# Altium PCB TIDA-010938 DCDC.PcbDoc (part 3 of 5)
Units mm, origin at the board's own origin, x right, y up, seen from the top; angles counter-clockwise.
Board outline 275 x 165 mm, 4 copper layers (Top Layer, Layer 1, Layer 2, Bottom Layer), stack 1.787 mm thick; 436 components, 216 nets, 1367 pads, 1992 vias.
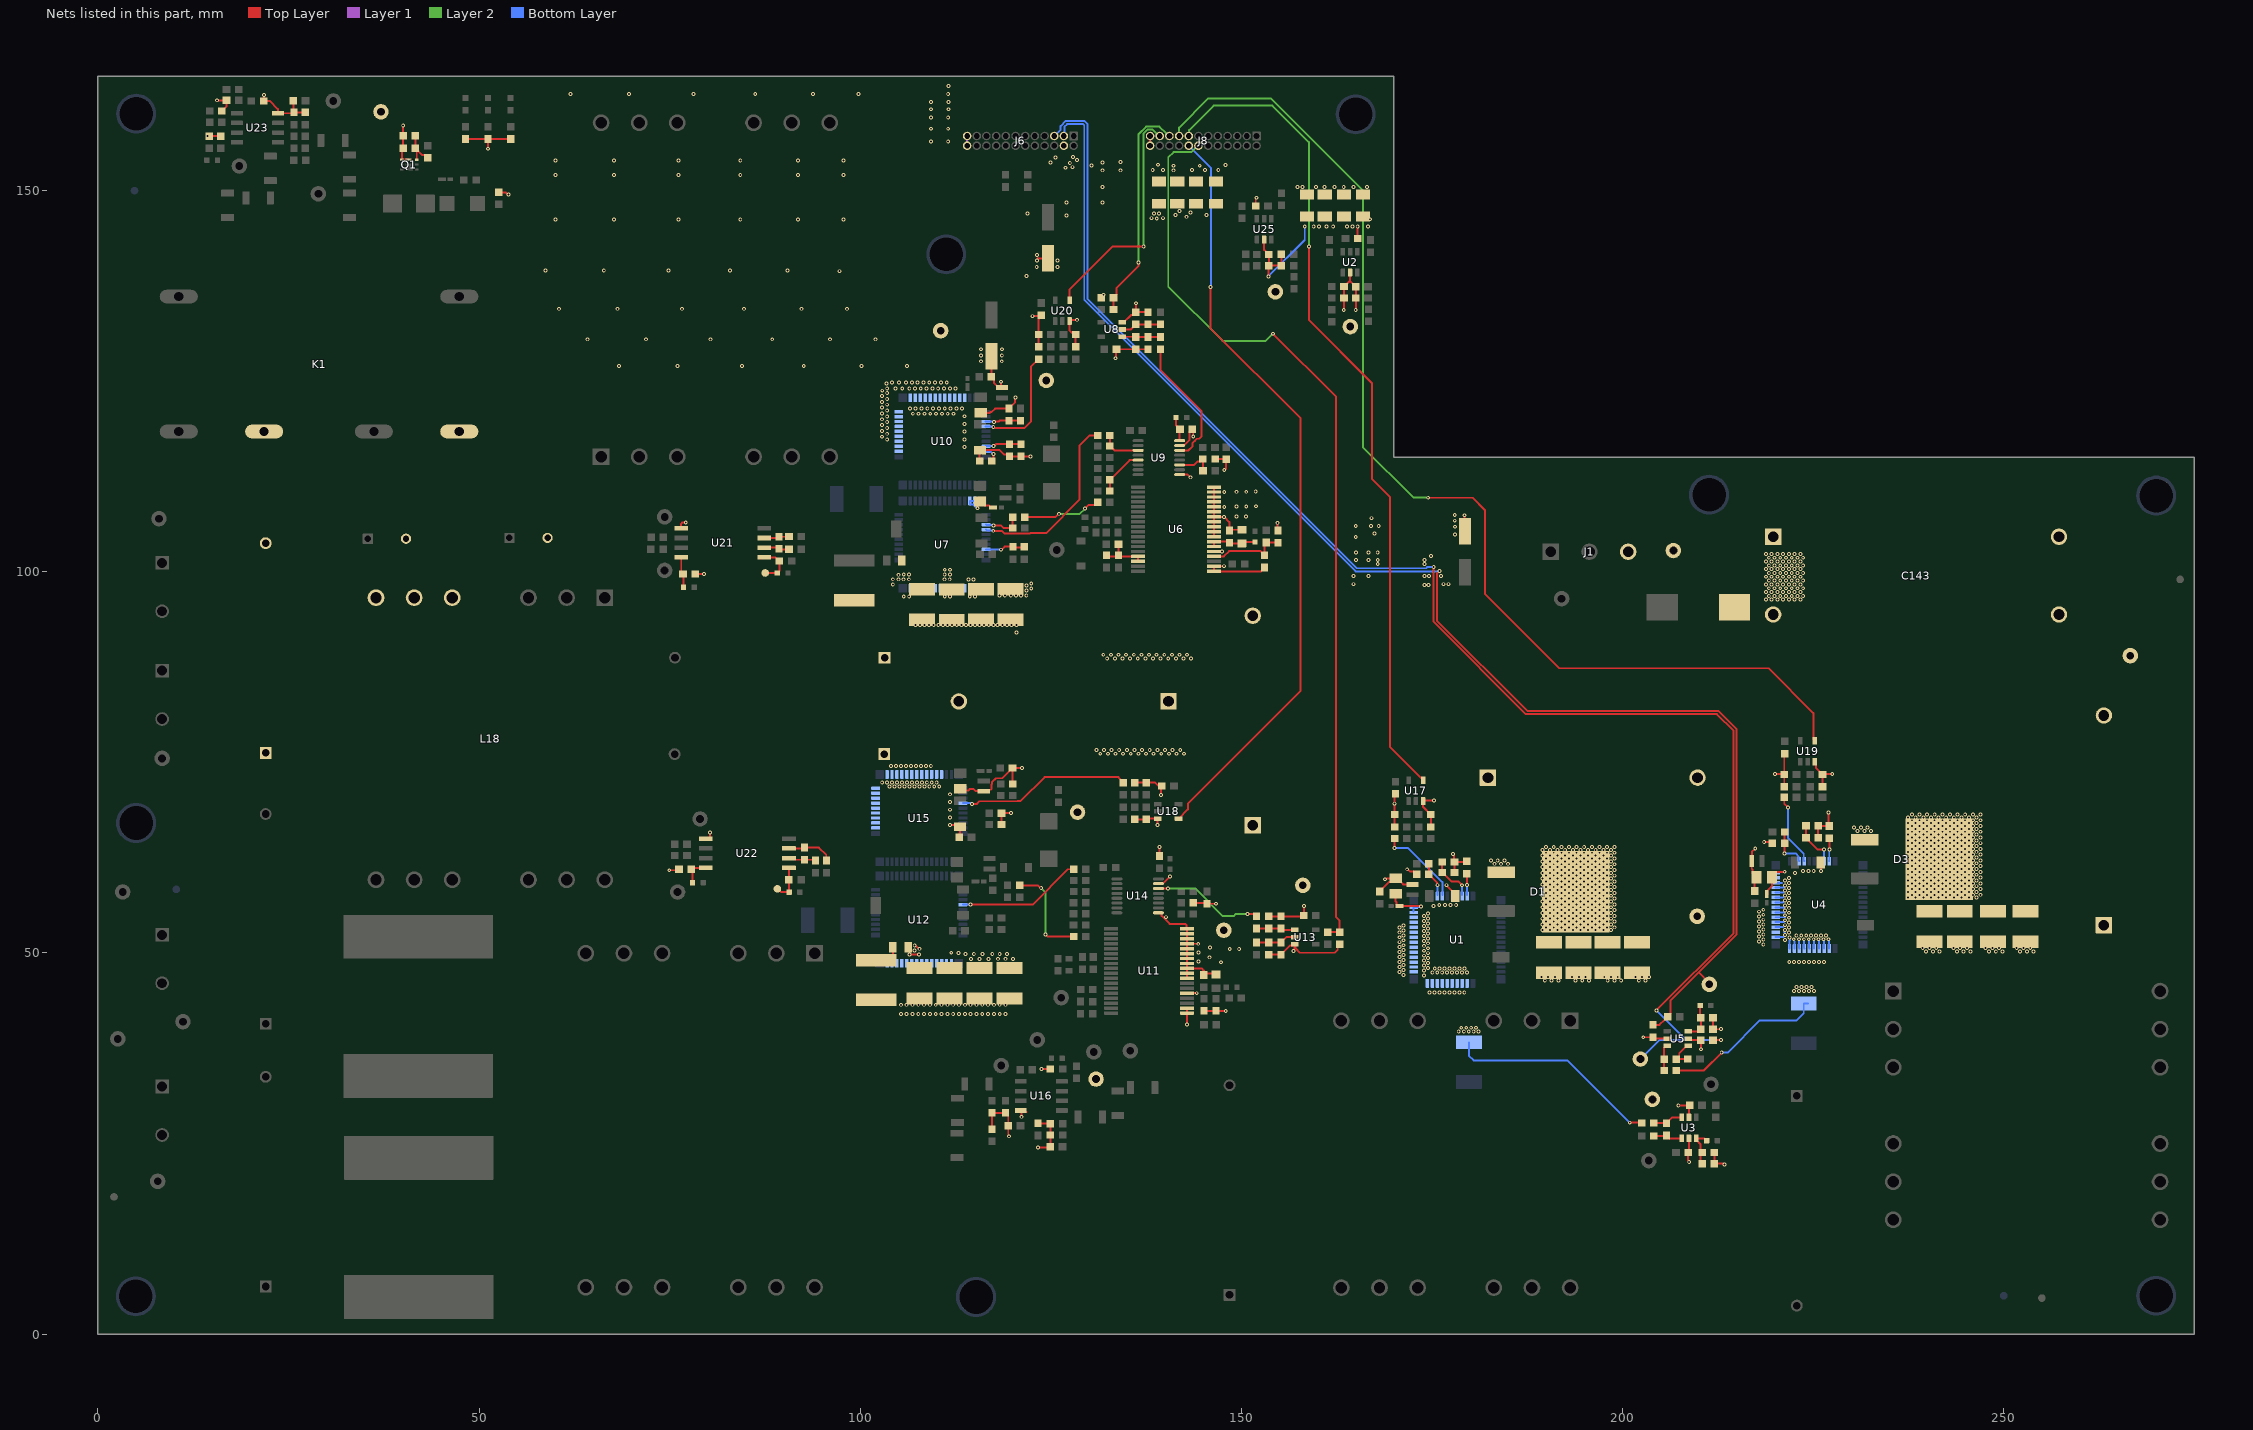
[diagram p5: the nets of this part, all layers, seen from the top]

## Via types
v1: diameter 0.508, hole 0.254, Top Layer to Bottom Layer, tented both sides, 1977 vias
v2: diameter 0.508, hole 0.254, Top Layer to Bottom Layer, 15 vias

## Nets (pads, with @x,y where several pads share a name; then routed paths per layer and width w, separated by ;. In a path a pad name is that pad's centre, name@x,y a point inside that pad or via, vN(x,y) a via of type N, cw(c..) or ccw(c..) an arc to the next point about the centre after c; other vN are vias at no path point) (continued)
CS_Boost2+: C112.2 J6.3 R19.2 TP18.1 | length 186.2
  Top Layer w0.254: v1(175.992,100.087) 175.647,99.741 175.647,93.592 187.494,81.745 212.549,81.745 214.97,79.325 214.97,52.43 209.99,47.45 ; C112.2@203.975,40.566 204.831,40.566 205.527,41.262 205.527,41.275 R19.2@205.875,41.623 ; R19.2@205.9,41.623 205.925,41.623 206.273,41.971 206.273,43.733 209.99,47.45 ; TP18.1@211.384,45.887 211.384,46.056 209.99,47.45
  Bottom Layer w0.254: J6.3@126.715,157.166 126.776,157.227 126.776,158.375 127.133,158.732 129.235,158.732 129.384,158.583 129.384,135.666 164.99,100.06 175.966,100.06 v1(175.992,100.087)
CS_Boost2-: J6.5 R72.2 TP19.1 | length 200.2
  Top Layer w0.254: v1(175.222,100.647) 175.222,93.445 187.326,81.341 212.382,81.341 214.566,79.157 214.566,52.597 v1(204.429,42.46) ; R72.2@211.842,38.564 R72.2@211.867,38.564 v1@212.932,38.564
  Bottom Layer w0.254: J6.5@125.445,157.166 126.288,158.01 126.288,158.459 126.966,159.136 129.403,159.136 129.788,158.751 129.788,135.833 165.158,100.464 174.213,100.464 174.396,100.647 175.22,100.647 v1@175.221,100.645 ; TP19.1@202.338,36.083 204.845,38.591 208.298,38.591 ; v1(204.429,42.46) 208.298,38.591 ; v1(212.932,38.591) 208.298,38.591
DC_Bus+: C3.1 C4.1 C10.1 C24.1 C100.1 C101.1 C106.1 C107.1 C110.1 C111.1 C113.1 C126.1 C127.1 C130.1 C131.1 C133.1 C134.1 C135.1 C140.1 C141.1 C143.1 C143.3 D1.1 D1.3 D3.1 D3.3 L3.1 R94.2 R98.2 U7.2 U7.3 U7.4 U7.5 U7.6 U7.7 U7.8 U7.9 U7.10 U7.11 U7.12 U7.13 U7.14 U7.15 U12.2 U12.3 U12.4 U12.5 U12.6 U12.7 U12.8 U12.9 U12.10 U12.11 U12.12 U12.13 U12.14 U12.15 | length 2
  Top Layer w0.254: v1(106.469,49.816) 106.473,49.812 107.683,49.812 v1(107.688,49.807) ; v1(107.138,50.991) 107.187,50.943 107.29,50.943 107.688,50.545 v1(107.756,50.545)
  other v1: 114.539,49.228 115.646,49.228 116.804,49.228 118.07,49.236 119.044,49.236 120.018,49.228 113.787,49.86 114.894,49.86 116.052,49.86 119.266,49.86 117.318,49.868 118.292,49.868 112.91,49.98 111.937,50.028 107.106,50.347 189.472,52.99 190.472,52.99 191.472,52.99 192.472,52.99 193.472,52.99 194.472,52.99 195.472,52.99 196.472,52.99 197.472,52.99 198.466,52.99 189.965,53.367 190.965,53.367 191.965,53.367 192.965,53.367 193.965,53.367 194.965,53.367 195.965,53.367 196.965,53.367 197.965,53.367 198.959,53.367 189.472,53.741 190.472,53.741 191.472,53.741 192.472,53.741 193.472,53.741 194.472,53.741 195.472,53.741 196.472,53.741 197.472,53.741 198.466,53.742 189.965,54.119 190.965,54.119 191.965,54.119 192.965,54.119 193.965,54.119 194.965,54.119 195.965,54.119 196.965,54.119 197.965,54.119 198.959,54.119 189.472,54.493 190.472,54.493 191.472,54.493 192.472,54.493 193.472,54.493 194.472,54.493 195.472,54.493 196.472,54.493 197.472,54.493 198.466,54.494 189.965,54.871 190.965,54.871 191.965,54.871 192.965,54.871 193.965,54.871 194.965,54.871 195.965,54.871 196.965,54.871 197.965,54.871 198.959,54.871 189.472,55.245 190.472,55.245 191.472,55.245 192.472,55.245 193.472,55.245 194.472,55.245 195.472,55.245 196.472,55.245 197.472,55.245 198.466,55.246 189.965,55.623 190.965,55.623 191.965,55.623 192.965,55.623 193.965,55.623 194.965,55.623 195.965,55.623 196.965,55.623 197.965,55.623 198.959,55.623 189.472,55.997 190.472,55.997 191.472,55.997 192.472,55.997 193.472,55.997 194.472,55.997 195.472,55.997 196.472,55.997 197.472,55.997 198.466,55.998 189.965,56.375 190.965,56.375 191.965,56.375 192.965,56.375 193.965,56.375 194.965,56.375 195.965,56.375 196.965,56.375 197.965,56.375 198.959,56.375 189.472,56.749 190.472,56.749 191.472,56.749 192.472,56.749 193.472,56.749 194.472,56.749 195.472,56.749 196.472,56.749 197.472,56.749 198.466,56.749 189.965,57.127 190.965,57.127 191.965,57.127 192.965,57.127 193.965,57.127 194.965,57.127 195.965,57.127 196.965,57.127 197.965,57.127 198.959,57.127 237.448,57.253 238.448,57.253 239.448,57.253 240.448,57.253 241.448,57.253 242.448,57.253 243.448,57.253 244.448,57.253 245.448,57.253 246.442,57.253 189.472,57.501 190.472,57.501 191.472,57.501 192.472,57.501 193.472,57.501 194.472,57.501 195.472,57.501 196.472,57.501 197.472,57.501 198.466,57.501 237.941,57.63 238.941,57.63 239.941,57.63 240.941,57.63 241.941,57.63 242.941,57.63 243.941,57.63 244.941,57.63 245.941,57.63 246.935,57.631 189.965,57.879 190.965,57.879 191.965,57.879 192.965,57.879 193.965,57.879 194.965,57.879 195.965,57.879 196.965,57.879 197.965,57.879 198.959,57.879 237.448,58.005 238.448,58.005 239.448,58.005 240.448,58.005 241.448,58.005 242.448,58.005 243.448,58.005 244.448,58.005 245.448,58.005 246.442,58.005 189.472,58.253 190.472,58.253 191.472,58.253 192.472,58.253 193.472,58.253 194.472,58.253 195.472,58.253 196.472,58.253 197.472,58.253 198.466,58.253 237.941,58.382 238.941,58.382 239.941,58.382 240.941,58.382 241.941,58.382 242.941,58.382 243.941,58.382 244.941,58.382 245.941,58.382 246.935,58.383 189.965,58.63 190.965,58.63 191.965,58.63 192.965,58.63 193.965,58.63 194.965,58.63 195.965,58.63 196.965,58.63 197.965,58.63 198.959,58.631 237.448,58.757 238.448,58.757 239.448,58.757 240.448,58.757 241.448,58.757 242.448,58.757 243.448,58.757 244.448,58.757 245.448,58.757 246.442,58.757 189.472,59.005 190.472,59.005 191.472,59.005 192.472,59.005 193.472,59.005 194.472,59.005 195.472,59.005 196.472,59.005 197.472,59.005 198.466,59.005 237.941,59.134 238.941,59.134 239.941,59.134 240.941,59.134 241.941,59.134 242.941,59.134 243.941,59.134 244.941,59.134 245.941,59.134 246.935,59.135 189.965,59.382 190.965,59.382 191.965,59.382 192.965,59.382 193.965,59.382 194.965,59.382 195.965,59.382 196.965,59.382 197.965,59.382 198.959,59.383 237.448,59.509 238.448,59.509 239.448,59.509 240.448,59.509 241.448,59.509 242.448,59.509 243.448,59.509 244.448,59.509 245.448,59.509 246.442,59.509 189.472,59.757 190.472,59.757 191.472,59.757 192.472,59.757 193.472,59.757 194.472,59.757 195.472,59.757 196.472,59.757 197.472,59.757 198.466,59.757 237.941,59.886 238.941,59.886 239.941,59.886 240.941,59.886 241.941,59.886 242.941,59.886 243.941,59.886 244.941,59.886 245.941,59.886 246.935,59.886 189.965,60.134 190.965,60.134 191.965,60.134 192.965,60.134 193.965,60.134 194.965,60.134 195.965,60.134 196.965,60.134 197.965,60.134 198.959,60.135 237.448,60.26 238.448,60.26 239.448,60.26 240.448,60.26 241.448,60.26 242.448,60.26 243.448,60.26 244.448,60.26 245.448,60.26 246.442,60.261 189.472,60.509 190.472,60.509 191.472,60.509 192.472,60.509 193.472,60.509 194.472,60.509 195.472,60.509 196.472,60.509 197.472,60.509 198.466,60.509 237.941,60.638 238.941,60.638 239.941,60.638 240.941,60.638 241.941,60.638 242.941,60.638 243.941,60.638 244.941,60.638 245.941,60.638 246.935,60.638 189.965,60.886 190.965,60.886 191.965,60.886 192.965,60.886 193.965,60.886 194.965,60.886 195.965,60.886 196.965,60.886 197.965,60.886 198.959,60.887 237.448,61.012 238.448,61.012 239.448,61.012 240.448,61.012 241.448,61.012 242.448,61.012 243.448,61.012 244.448,61.012 245.448,61.012 246.442,61.013 189.472,61.261 190.472,61.261 191.472,61.261 192.472,61.261 193.472,61.261 194.472,61.261 195.472,61.261 196.472,61.261 197.472,61.261 198.466,61.261 237.941,61.39 238.941,61.39 239.941,61.39 240.941,61.39 241.941,61.39 242.941,61.39 243.941,61.39 244.941,61.39 245.941,61.39 246.935,61.39 189.965,61.638 190.965,61.638 191.965,61.638 192.965,61.638 193.965,61.638 194.965,61.638 195.965,61.638 196.965,61.638 197.965,61.638 198.959,61.639 183.182,61.698 184.069,61.698 184.957,61.698 237.448,61.764 238.448,61.764 239.448,61.764 240.448,61.764 241.448,61.764 242.448,61.764 243.448,61.764 244.448,61.764 245.448,61.764 246.442,61.765 189.472,62.013 190.472,62.013 191.472,62.013 192.472,62.013 193.472,62.013 194.472,62.013 195.472,62.013 196.472,62.013 197.472,62.013 198.466,62.013 182.729,62.12 183.616,62.12 184.503,62.12 237.941,62.142 238.941,62.142 239.941,62.142 240.941,62.142 241.941,62.142 242.941,62.142 243.941,62.142 244.941,62.142 245.941,62.142 246.935,62.142 189.965,62.39 190.965,62.39 191.965,62.39 192.965,62.39 193.965,62.39 194.965,62.39 195.965,62.39 196.965,62.39 197.965,62.39 198.959,62.39 237.448,62.516 238.448,62.516 239.448,62.516 240.448,62.516 241.448,62.516 242.448,62.516 243.448,62.516 244.448,62.516 245.448,62.516 246.442,62.517 189.472,62.764 190.472,62.764 191.472,62.764 192.472,62.764 193.472,62.764 194.472,62.764 195.472,62.764 196.472,62.764 197.472,62.764 198.466,62.765 237.941,62.894 238.941,62.894 239.941,62.894 240.941,62.894 241.941,62.894 242.941,62.894 243.941,62.894 244.941,62.894 245.941,62.894 246.935,62.894 189.965,63.142 190.965,63.142 191.965,63.142 192.965,63.142 193.965,63.142 194.965,63.142 195.965,63.142 196.965,63.142 197.965,63.142 198.959,63.142 237.448,63.268 238.448,63.268 239.448,63.268 240.448,63.268 241.448,63.268 242.448,63.268 243.448,63.268 244.448,63.268 245.448,63.268 246.442,63.269 189.472,63.516 190.472,63.516 191.472,63.516 192.472,63.516 193.472,63.516 194.472,63.516 195.472,63.516 196.472,63.516 197.472,63.516 198.466,63.517 237.941,63.646 238.941,63.646 239.941,63.646 240.941,63.646 241.941,63.646 242.941,63.646 243.941,63.646 244.941,63.646 245.941,63.646 246.935,63.646 189.965,63.894 190.965,63.894 191.965,63.894 192.965,63.894 193.965,63.894 194.965,63.894 195.965,63.894 196.965,63.894 197.965,63.894 198.959,63.894 237.448,64.02 238.448,64.02 239.448,64.02 240.448,64.02 241.448,64.02 242.448,64.02 243.448,64.02 244.448,64.02 245.448,64.02 246.442,64.02 237.941,64.398 238.941,64.398 239.941,64.398 240.941,64.398 241.941,64.398 242.941,64.398 243.941,64.398 244.941,64.398 245.941,64.398 246.935,64.398 237.448,64.772 238.448,64.772 239.448,64.772 240.448,64.772 241.448,64.772 242.448,64.772 243.448,64.772 244.448,64.772 245.448,64.772 246.442,64.772 237.941,65.15 238.941,65.15 239.941,65.15 240.941,65.15 241.941,65.15 242.941,65.15 243.941,65.15 244.941,65.15 245.941,65.15 246.935,65.15 237.448,65.524 238.448,65.524 239.448,65.524 240.448,65.524 241.448,65.524 242.448,65.524 243.448,65.524 244.448,65.524 245.448,65.524 246.442,65.524 237.941,65.901 238.941,65.901 239.941,65.901 240.941,65.901 241.941,65.901 242.941,65.901 243.941,65.901 244.941,65.901 245.941,65.901 246.935,65.902 230.829,66.022 231.716,66.022 232.603,66.022 237.448,66.276 238.448,66.276 239.448,66.276 240.448,66.276 241.448,66.276 242.448,66.276 243.448,66.276 244.448,66.276 245.448,66.276 246.442,66.276 230.375,66.443 231.263,66.443 232.15,66.443 237.941,66.653 238.941,66.653 239.941,66.653 240.941,66.653 241.941,66.653 242.941,66.653 243.941,66.653 244.941,66.653 245.941,66.653 246.935,66.654 237.448,67.028 238.448,67.028 239.448,67.028 240.448,67.028 241.448,67.028 242.448,67.028 243.448,67.028 244.448,67.028 245.448,67.028 246.442,67.028 237.941,67.405 238.941,67.405 239.941,67.405 240.941,67.405 241.941,67.405 242.941,67.405 243.941,67.405 244.941,67.405 245.941,67.405 246.935,67.406 237.448,67.78 238.448,67.78 239.448,67.78 240.448,67.78 241.448,67.78 242.448,67.78 243.448,67.78 244.448,67.78 245.448,67.78 246.442,67.78 237.941,68.157 238.941,68.157 239.941,68.157 240.941,68.157 241.941,68.157 242.941,68.157 243.941,68.157 244.941,68.157 245.941,68.157 246.935,68.158 131.481,76.13 132.482,76.13 133.482,76.13 134.482,76.13 135.483,76.13 136.483,76.13 137.484,76.13 138.484,76.13 139.485,76.13 140.485,76.13 141.486,76.13 142.486,76.13 130.966,76.63 131.966,76.63 132.967,76.63 133.967,76.63 134.967,76.63 135.968,76.63 136.968,76.63 137.969,76.63 138.969,76.63 139.97,76.63 140.97,76.63 141.971,76.63 132.393,88.622 133.394,88.622 134.394,88.622 135.395,88.622 136.395,88.622 137.396,88.622 138.396,88.622 139.397,88.622 140.397,88.622 141.397,88.622 142.398,88.622 143.398,88.622 131.878,89.122 132.878,89.122 133.879,89.122 134.879,89.122 135.88,89.122 136.88,89.122 137.881,89.122 138.881,89.122 139.882,89.122 140.882,89.122 141.883,89.122 142.883,89.122 218.805,96.348 219.557,96.348 220.309,96.348 221.061,96.348 221.813,96.348 222.565,96.348 223.317,96.348 105.702,96.763 106.42,96.763 111.079,96.763 111.763,96.763 114.358,96.763 115.042,96.763 219.18,96.841 219.932,96.841 220.684,96.841 221.436,96.841 222.187,96.841 222.939,96.841 223.691,96.841 118.275,96.912 118.959,96.912 119.747,96.912 120.431,96.912 121.093,96.912 121.777,96.912 218.805,97.348 219.557,97.348 220.309,97.348 221.061,97.348 221.813,97.348 222.565,97.348 223.317,97.348 121.787,97.529 122.429,97.788 219.18,97.841 219.932,97.841 220.684,97.841 221.436,97.841 222.187,97.841 222.939,97.841 223.691,97.841 121.81,98.224 104.268,98.337 218.805,98.348 219.557,98.348 220.309,98.348 221.061,98.348 221.813,98.348 222.565,98.348 223.317,98.348 122.429,98.472 219.18,98.841 219.932,98.841 220.684,98.841 221.436,98.841 222.187,98.841 222.939,98.841 223.691,98.841 114.218,99.004 114.868,99.004 104.268,99.018 105.01,99.018 105.681,99.018 106.365,99.018 111.046,99.018 111.73,99.018 218.805,99.348 219.557,99.348 220.309,99.348 221.061,99.348 221.813,99.348 222.565,99.348 223.317,99.348 105.031,99.607 105.702,99.621 106.393,99.621 111.074,99.621 111.758,99.621 219.18,99.841 219.932,99.841 220.684,99.841 221.436,99.841 222.187,99.841 222.939,99.841 223.691,99.841 111.079,100.27 111.763,100.27 218.805,100.348 219.557,100.348 220.309,100.348 221.061,100.348 221.813,100.348 222.565,100.348 223.317,100.348 219.18,100.841 219.932,100.841 220.684,100.841 221.436,100.841 222.187,100.841 222.939,100.841 223.691,100.841 218.805,101.348 219.557,101.348 220.309,101.348 221.061,101.348 221.813,101.348 222.565,101.348 223.317,101.348 219.18,101.841 219.932,101.841 220.684,101.841 221.436,101.841 222.187,101.841 222.939,101.841 223.691,101.841 218.805,102.348 219.557,102.348 220.309,102.348 221.061,102.348 221.813,102.348 222.565,102.348 223.317,102.348
DC_Bus-: C2.1 C3.2 C4.2 C5.2 C6.2 C7.1 C8.1 C10.2 C11.1 C12.1 C13.2 C14.1 C15.1 C20.2 C21.1 C22.1 C24.2 C25.1 C26.1 C27.2 C28.1 C29.1 C39.1 C43.2 C47.1 C50.2 C52.2 C58.1 C59.2 C60.1 C61.1 C62.1 C63.2 C64.1 C65.2 C66.2 C67.1 C73.1 C77.2 C78.1 C81.1 C82.1 C83.1 C84.2 C86.1 C87.1 C91.1 C92.1 C93.2 C94.1 C95.1 C96.1 C97.1 C98.1 C99.2 C100.2 C101.2 C106.2 C107.2 C110.2 C111.2 C113.2 C115.2 C116.1 C117.2 C118.1 C119.2 C120.1 C122.1 C124.2 C125.2 C126.2 C127.2 C128.2 C129.2 C130.2 C131.2 C133.2 C134.2 C135.2 C140.2 C141.2 C142.1 C143.2 C143.4 C146.2 C152.1 J1.3 K1.2 L2.1 L5.1 L10.1 L14.1 R2.2 R6.1 R9.1 R16.1 R17.2 R18.2 R20.1 R27.1 R39.1 R45.1 R52.1 R64.1 R70.1 R79.1 R80.1 R81.1 R82.1 R90.1 R91.1 R92.1 R93.1 R105.1 R125.1 R127.1 R129.1 R131.1 R132.1 R135.1 R138.1 R148.1 R156.1 R157.1 R160.1 R161.1 R162.1 R163.1 R164.1 R165.1 R166.1 TP1.1 TP2.1 TP4.1 TP5.1 TP13.1 TP17.1 TP22.1 TP37.1 TP42.1 U1.18 U1.19 U1.20 U1.21 U1.22 U1.23 U1.24 U1.25 U1.26 U1.28 U1.29 U1.30 U1.31 U1.32 U1.33 U1.34 U1.35 U1.36 U1.37 U1.38 U1.39 U2.2 U4.18 U4.19 U4.20 U4.21 U4.22 U4.23 U4.24 U4.25 U4.26 U4.28 U4.29 U4.30 U4.31 U4.32 U4.33 U4.34 U4.35 U4.36 U4.37 U4.38 U4.39 U6.1 U6.2 U6.5 U6.8 U6.9 U6.10 U6.11 U6.12 U6.13 U6.14 U6.15 U6.16 U6.17 U6.18 U8.3 U9.9 U9.15 U10.18 U10.19 U10.20 U10.21 U10.22 U10.23 U10.24 U10.25 U10.26 U10.28 U10.29 U10.30 U10.31 U10.32 U10.33 U10.34 U10.35 U10.36 U10.37 U10.38 U10.39 U11.1 U11.2 U11.5 U11.8 U11.9 U11.10 U11.11 U11.12 U11.13 U11.14 U11.15 U11.16 U11.17 U11.18 U13.3 U14.9 U14.15 U15.18 U15.19 U15.20 U15.21 U15.22 U15.23 U15.24 U15.25 U15.26 U15.28 U15.29 U15.30 U15.31 U15.32 U15.33 U15.34 U15.35 U15.36 U15.37 U15.38 U15.39 U17.3 U18.3 U19.3 U20.3 U25.2 | length 300.3
  Top Layer w0.254: v1(111.774,66.769) 112.841,66.769 C93.2@113.062,66.547 113.062,65.248 C95.1@112.987,65.173 ; C99.2@113.121,71.524 113.344,71.301 114.154,71.301 114.347,71.495 114.889,71.495 115.166,71.218 116.195,71.218 L14.1@116.198,71.215 116.396,71.413 117.09,71.413 117.239,71.562 117.239,72.118 117.275,72.154 117.275,72.386 117.804,72.915 118.604,72.915 119.944,74.255 R138.1@119.969,74.255 ; C61.1@115.668,114.535 115.668,115.944 C59.2@115.693,115.969 118.276,115.969 118.869,115.376 119.353,115.376 C64.1@119.576,115.152 R45.1@121.085,115.152 121.126,115.11 v1(122.317,115.11) ; C65.2@115.797,120.859 116.979,120.859 117.089,120.97 117.241,120.97 117.691,121.42 C62.1@119.505,121.42 119.505,121.445 120.316,122.255 120.316,122.826 v1(120.364,122.875) ; R135.1@117.195,125.597 117.22,125.622 C115.2@117.22,128.292 ; R135.1@117.22,125.597 117.568,125.249 117.568,124.744 118.136,124.176 L10.1@118.611,124.176 118.461,124.325 v1(118.461,124.932) ; C98.1@118.53,66.849 R70.1@118.53,68.319 118.567,68.356 v1(119.76,68.356) ; C96.1@120.018,72.163 119.969,72.213 R138.1@119.969,74.255 ; v1(121.239,74.255) R138.1@119.969,74.255 ; v1(122.587,133.53) 123.602,133.53 C129.2@123.725,133.653 ; R91.1@123.4,129.286 R91.1@123.4,129.518 C87.1@123.4,131.116 123.4,133.145 C129.2@123.725,133.47 ; U20.3@127.458,132.578 127.458,131.617 128.233,130.842 128.258,130.842 R93.1@128.258,129.52 R93.1@128.258,129.286 ; U20.3@127.458,132.895 127.621,133.058 v1(128.414,133.058) ; C14.1@131.611,135.936 131.611,136.192 131.782,136.192 v1(131.929,136.339) ; v1(133.458,128.014) 133.458,128.083 133.551,128.175 133.551,129.143 C52.2@133.606,129.198 C11.1@136.143,129.198 R39.1@137.741,129.198 ; U8.3@134.364,132.735 134.564,132.735 135.516,133.687 135.795,133.687 C15.1@136.143,134.035 ; R82.1@136.008,67.519 C83.1@137.508,67.519 137.602,67.613 U18.3@139.001,67.613 139.009,67.605 v1(139.009,66.791) ; R80.1@136.008,72.344 C78.1@137.508,72.344 138.675,72.344 C125.2@139.114,71.905 ; C15.1@136.141,134.06 136.16,134.078 v1(136.16,135.23) ; C15.1@136.143,134.06 R64.1@137.739,134.06 ; U14.9@139.116,55.273 139.468,55.273 139.536,55.205 139.536,54.853 140.58,53.809 142.624,53.809 142.806,53.627 142.806,53.225 U11.18@142.862,53.17 U11.17@142.862,52.52 U11.16@142.862,51.87 U11.15@142.862,51.22 ; U14.15@139.116,59.083 139.681,59.083 139.839,59.241 140.626,60.028 v1(140.626,60.041) v1@140.669,60.083 ; C125.2@139.163,72.019 C125.2@139.19,71.991 ; C84.2@139.246,62.725 139.271,62.75 v1(139.271,63.917) ; C125.2@139.374,71.504 C125.2@139.374,71.92 ; v1(139.451,70.719) C125.2@139.451,72.006 ; U9.9@141.902,112.752 142.958,112.752 v1(143.314,112.396) ; U9.15@141.902,116.562 141.93,116.59 142.495,116.59 143.161,117.257 143.161,118.356 143.509,118.704 C50.2@143.534,118.704 143.774,118.356 143.682,118.356 v1(143.682,117.732) ; v1(142.862,40.6) U11.1@142.862,42.12 U11.2@142.862,42.77 ; U11.5@142.862,44.72 142.863,44.721 v1(144.137,44.722) v1(144.137,44.722) ; U11.8@142.862,46.67 U11.9@142.862,47.32 U11.10@142.862,47.97 ; C92.1@143.438,56.586 C92.1@143.688,56.586 C152.1@145.407,56.586 ; C92.1@143.749,56.525 C152.1@145.468,56.525 ; v1(144.335,51.203) 144.327,51.212 142.87,51.212 U11.15@142.862,51.22 ; C77.2@145.062,47.11 145.239,47.287 C73.1@146.647,47.287 ; C81.1@145.087,42.407 R52.1@146.672,42.407 v1(147.939,42.407) ; 145.087,47.692 144.81,47.97 U11.10@142.862,47.97 ; C152.1@145.468,56.456 v1(146.668,56.456) ; U6.5@146.395,102.667 146.406,102.656 147.428,102.656 v1(147.438,102.646) ; U6.8@146.395,104.617 U6.9@146.395,105.267 U6.10@146.395,105.917 U6.11@146.395,106.567 U6.12@146.395,107.217 ; U6.18@146.395,111.117 U6.17@146.395,110.467 U6.16@146.395,109.817 U6.15@146.395,109.167 U6.14@146.395,108.517 U6.13@146.395,107.867 U6.12@146.395,107.217 ; C58.1@146.547,114.8 C142.1@147.999,114.8 ; v1(147.689,100.736) 147.679,100.726 146.405,100.726 U6.2@146.395,100.717 U6.1@146.395,100.067 152.554,100.067 153.029,100.542 C47.1@153.029,100.567 ; v1(147.744,113.335) 147.812,113.335 147.991,113.514 147.999,113.514 C142.1@147.999,114.741 ; C39.1@150.063,105.517 148.524,105.517 C43.2@148.424,105.417 148.424,106.514 v1(147.737,107.201) 147.729,107.209 146.403,107.209 U6.12@146.395,107.217 ; C119.2@151.877,147.969 151.877,148.911 151.964,148.998 v1(151.964,149.066) ; U25.2@152.98,143.586 152.98,142.219 153.58,141.619 C120.1@153.605,141.619 R127.1@153.605,140.158 ; v1(153.538,138.754) 153.538,140.091 R127.1@153.605,140.158 ; R156.1@153.585,54.801 C25.1@155.201,54.801 158.043,54.801 C146.2@158.168,54.926 158.203,54.96 v1(158.203,56.164) ; R157.1@153.586,49.778 C29.1@155.203,49.778 155.203,49.803 156.355,50.955 156.807,50.955 U13.3@156.932,51.08 ; v1(154.737,106.43) 154.737,105.467 R27.1@154.787,105.417 ; C122.1@155.244,141.65 R125.1@155.244,140.158 R127.1@153.605,140.158 ; v1(156.831,50.278) 156.831,50.347 156.932,50.448 U13.3@156.932,51.08 ; C28.1@162.89,51.128 162.633,50.871 162.633,50.396 162.265,50.028 157.659,50.028 157.092,50.596 157.092,51.016 U13.3@156.98,51.128 U13.3@156.932,51.08 ; v1@163.434,134.47 163.459,134.495 R131.1@163.459,135.914 C116.1@163.459,137.417 163.484,137.417 164.175,138.108 164.251,138.108 ; U2.2@164.251,139.258 164.251,138.108 ; v1@165.001,134.455 R129.1@165.001,135.919 C118.1@165.001,137.383 164.976,137.383 164.251,138.108 ; v1(165.251,145.303) 165.251,143.724 C117.2@165.253,143.722 ; R105.1@168.131,58.056 168.131,58.081 169.343,59.292 169.729,59.292 C13.2@170.204,59.768 ; v1(168.831,59.669) 168.899,59.669 168.998,59.768 C13.2@170.204,59.768 ; R79.1@170.09,66.509 C67.1@170.09,68.155 v1(170.09,69.579) C124.2@170.09,71.003 ; v1(171.747,60.977) 171.815,60.977 172.132,60.66 172.628,60.66 C7.1@172.976,60.312 ; L2.1@172.425,58.984 171.218,58.984 170.402,59.8 C13.2@170.237,59.8 C13.2@170.204,59.768 ; R81.1@174.852,66.509 C82.1@174.852,68.155 174.827,68.155 173.835,69.147 U17.3@173.835,69.928 173.891,69.985 v1(175.246,69.985) ; v1(176.883,58.887) 178.061,57.709 C6.2@178.061,57.459 ; v1(177.77,63) 177.77,62.932 177.9,62.801 177.9,61.99 R6.1@177.951,61.94 ; C12.1@177.951,60.568 R6.1@177.951,61.94 ; v1(179.266,107.422) 179.266,105.412 C5.2@179.34,105.339 ; C8.1@179.567,62.015 179.492,61.94 R6.1@177.951,61.94 ; v1(200.938,27.732) 202.461,27.732 R9.1@202.504,27.69 ; R20.1@207.056,34.593 210.679,34.593 213,36.913 v1(213,36.966) ; R132.1@217.328,58.12 217.328,59.697 C27.2@217.517,59.886 ; v1(217.398,63.707) 217.398,63.676 216.97,63.248 216.97,62.097 L5.1@216.941,62.067 216.941,61.881 216.946,61.875 216.946,61.035 217.04,60.941 217.04,60.747 217.048,60.739 217.048,60.433 C27.2@217.556,59.925 ; v1(218.576,64.561) 219.489,64.561 C22.1@219.652,64.398 ; v1(219.977,73.467) 220.94,73.467 C86.1@221.207,73.735 ; R90.1@221.207,71.804 C86.1@221.207,73.424 C86.1@221.207,73.735 ; C128.2@221.282,76.148 221.207,76.073 C86.1@221.207,73.735 ; U19.3@225.212,75.073 225.385,74.9 225.385,74.243 226.204,73.424 226.241,73.46 v1(227.504,73.46) ; C26.1@225.655,65.124 R16.1@225.655,66.673 C21.1@226.991,66.673 ; C20.2@225.746,62.151 C20.2@226.016,61.881 226.006,61.87 v1(226.006,60.739) ; R92.1@226.229,71.804 C91.1@226.229,73.424 ; v1(226.991,68.436) C21.1@226.991,66.673 ; C21.1@227.123,66.66 227.11,66.673 C21.1@226.991,66.673 ; U11.10@142.862,47.97 U11.11@142.862,48.62 U11.12@142.862,49.27 U11.13@142.862,49.92 U11.14@142.862,50.57 U11.15@142.862,51.22
  Bottom Layer w0.254: v1(153.538,138.754) 158.309,143.525 v1(158.309,145.284) ; R17.2@179.842,38.283 179.842,36.541 180.469,35.914 192.757,35.914 v1(200.938,27.732) ; v1(213,36.966) 213.833,36.966 218.014,41.148 222.828,41.148 223.767,42.086 R18.2@223.767,43.363 R18.2@224.335,43.363 ; U4.28@220.082,52.085 221.1,52.085 ; U4.30@220.082,53.385 221.032,53.385 ; U4.31@220.082,54.035 221.164,54.035 ; U4.32@220.082,54.685 221.341,54.685 ; U4.33@220.082,55.335 221.186,55.335 221.248,55.273 ; U4.34@220.082,55.985 221.12,55.985 221.182,55.923 ; U4.35@220.082,56.635 221.032,56.635 221.29,56.893 v1(221.299,56.893) ; U4.36@220.082,57.285 221.015,57.285 221.032,57.302 ; U4.37@220.082,57.935 221.1,57.935 ; U4.38@220.082,58.585 221.139,58.585 221.158,58.566 ; U4.39@220.082,59.235 220.126,59.191 220.881,59.191 220.905,59.168 ; 221.187,52.735 221.248,52.674 ; U4.26@221.892,50.585 221.892,51.597 221.988,51.693 ; U4.25@222.542,50.585 222.542,51.442 222.576,51.476 ; v1(223.118,51.799) 223.155,51.762 223.155,50.622 U4.24@223.192,50.585 ; v1(223.768,51.799) 223.805,51.762 223.805,50.622 U4.23@223.842,50.585 ; v1(224.418,51.799) 224.455,51.762 224.455,50.622 U4.22@224.492,50.585 ; v1(225.068,51.799) 225.105,51.762 225.105,50.622 U4.21@225.142,50.585 ; v1(225.718,51.799) 225.755,51.762 225.755,50.622 U4.20@225.792,50.585 ; v1(226.368,51.799) 226.405,51.762 226.405,50.622 U4.19@226.442,50.585 ; v1(227.018,51.799) 227.055,51.762 227.055,50.622 U4.18@227.092,50.585
  other v1: 178.501,39.679 179.169,39.679 179.819,39.679 180.469,39.679 181.119,39.679 178.838,40.187 179.488,40.187 180.138,40.187 180.788,40.187 105.322,42.008 106.085,42.008 106.848,42.008 107.611,42.008 108.374,42.008 109.137,42.008 109.9,42.008 110.663,42.008 111.426,42.008 112.188,42.008 112.951,42.008 113.714,42.008 114.477,42.008 115.24,42.008 116.003,42.008 116.766,42.008 117.529,42.008 118.292,42.008 119.055,42.008 105.322,43.2 106.085,43.2 106.848,43.2 107.611,43.2 108.374,43.2 109.137,43.2 109.9,43.2 110.663,43.2 111.426,43.2 112.188,43.2 112.951,43.2 113.714,43.2 114.477,43.2 115.24,43.2 116.003,43.2 116.766,43.2 117.529,43.2 118.292,43.2 119.055,43.2 174.686,44.796 175.336,44.796 175.986,44.796 176.636,44.796 177.286,44.796 177.936,44.796 178.586,44.796 179.236,44.796 222.49,45.005 223.158,45.005 223.808,45.005 224.458,45.005 225.108,45.005 222.828,45.513 223.478,45.513 224.128,45.513 224.778,45.513 189.796,46.405 190.683,46.405 191.57,46.405 193.823,46.405 194.71,46.405 195.597,46.405 198.044,46.405 198.932,46.405 199.819,46.405 202.126,46.405 203.014,46.405 189.342,46.827 190.229,46.827 191.116,46.827 193.369,46.827 194.256,46.827 195.143,46.827 197.591,46.827 198.478,46.827 199.365,46.827 201.673,46.827 202.56,46.827 203.447,46.827 173.963,47.039 171.283,47.114 175.036,47.437 175.686,47.437 176.336,47.437 176.986,47.437 177.636,47.437 178.286,47.437 178.936,47.437 179.586,47.437 170.736,47.51 173.963,47.689 171.283,47.764 175.356,47.945 176.006,47.945 176.656,47.945 177.306,47.945 177.956,47.945 178.606,47.945 179.256,47.945 174.471,48.02 170.736,48.16 173.963,48.339 171.283,48.414 174.471,48.67 147.311,48.784 170.736,48.81 221.858,48.796 222.508,48.796 223.158,48.796 223.808,48.796 224.458,48.796 225.108,48.796 225.758,48.796 226.408,48.796 144.378,48.865 173.963,48.989 171.283,49.064 174.471,49.32 145.817,49.429 170.736,49.46 173.963,49.639 171.283,49.714 174.471,49.97 144.352,50.069 170.736,50.11 239.821,50.211 240.708,50.211 241.595,50.211 243.848,50.211 244.735,50.211 245.622,50.211 248.07,50.211 248.957,50.211 249.844,50.211 252.152,50.211 253.039,50.211 253.926,50.211 173.963,50.289 171.283,50.364 148.465,50.511 149.706,50.511 174.471,50.62 239.367,50.632 240.254,50.632 241.141,50.632 243.394,50.632 244.281,50.632 245.168,50.632 247.616,50.632 248.503,50.632 249.39,50.632 251.698,50.632 252.585,50.632 253.472,50.632 145.856,50.692 170.736,50.76 173.963,50.939 171.283,51.014 218.456,51.115 174.471,51.27 170.736,51.41 217.908,51.511 173.963,51.589 171.283,51.664 221.299,51.693 218.456,51.765 222.45,51.799 174.471,51.92 170.736,52.06 221.892,52.049 217.908,52.161 173.963,52.239 171.283,52.314 222.788,52.307 223.438,52.307 224.088,52.307 224.738,52.307 225.388,52.307 226.038,52.307 226.688,52.307 221.299,52.343 218.456,52.415 174.471,52.57 221.807,52.673 170.736,52.71 217.908,52.811 173.963,52.889 171.283,52.964 221.299,52.993 218.456,53.065 174.471,53.22 221.807,53.323 170.736,53.36 217.908,53.461 173.963,53.539 171.283,53.614 221.299,53.643 218.456,53.715 174.471,53.87 221.807,53.973 217.908,54.111 173.963,54.189 221.299,54.293 218.456,54.365 174.471,54.52 221.807,54.623 140.117,54.689 217.908,54.761 173.963,54.839 221.299,54.943 218.456,55.015 174.471,55.17 221.807,55.273 217.908,55.411 221.299,55.593 218.456,55.665 221.807,55.923 175.212,56.17 221.299,56.243 175.952,56.282 176.693,56.282 177.433,56.282 178.174,56.282 221.807,56.573 221.807,57.223 221.299,57.543 221.807,57.873 221.299,58.193 221.807,58.523 221.299,58.843 221.807,59.173 221.299,59.493 221.807,59.823 222.626,60.509 223.645,60.739 224.365,60.739 225.068,60.739 111.774,67.78 111.774,68.791 111.774,69.802 111.774,70.813 103.856,71.83 104.506,71.83 105.156,71.83 105.806,71.83 106.456,71.83 107.106,71.83 107.756,71.83 108.406,71.83 109.056,71.83 109.706,71.83 110.356,71.83 102.876,72.338 103.526,72.338 104.176,72.338 104.826,72.338 105.476,72.338 106.126,72.338 106.776,72.338 107.426,72.338 108.076,72.338 108.726,72.338 109.376,72.338 110.026,72.338 104.051,74.526 104.701,74.526 105.351,74.526 106.001,74.526 106.651,74.526 107.301,74.526 107.951,74.526 108.601,74.526 109.251,74.526 120.472,92.055 107.227,93.017 107.829,93.017 108.43,93.017 109.032,93.017 109.634,93.017 110.236,93.017 110.851,93.004 111.452,93.004 112.054,93.004 112.656,93.004 113.258,93.004 113.847,93.017 114.449,93.017 115.051,93.017 115.653,93.017 116.254,93.017 116.856,93.017 117.458,93.017 118.011,93.017 118.631,93.017 119.245,93.017 119.858,93.017 120.472,93.017 177.999,104.883 177.999,105.909 177.981,106.705 149.375,107.239 150.623,107.239 177.981,107.43 147.744,108.511 149.375,108.549 150.63,108.549 151.928,108.595 147.744,110.459 149.375,110.497 150.63,110.497 151.873,110.553 113.684,116.362 103.532,117.342 113.684,117.373 102.853,117.714 103.532,118.105 113.684,118.384 102.853,118.477 103.532,118.868 102.853,119.24 113.684,119.395 103.532,119.631 102.853,120.003 103.532,120.394 113.684,120.406 106.892,120.73 107.655,120.73 108.418,120.73 109.181,120.73 109.944,120.73 110.707,120.73 111.47,120.73 112.233,120.73 102.853,120.766 103.532,121.157 106.501,121.409 107.264,121.409 108.027,121.409 108.79,121.409 109.553,121.409 110.316,121.409 111.079,121.409 111.842,121.409 112.605,121.409 113.368,121.409 102.853,121.529 103.532,121.92 102.853,122.292 103.532,122.683 102.853,123.055 103.532,123.446 102.886,123.755 103.532,124.057 104.609,124.057 105.503,124.067 106.431,124.057 107.172,124.067 107.935,124.067 108.698,124.067 109.461,124.067 110.224,124.067 110.987,124.067 111.75,124.067 112.513,124.067 103.445,124.707 104.159,124.846 105.058,124.846 106,124.846 106.763,124.846 107.526,124.846 108.289,124.846 109.052,124.846 109.815,124.846 110.578,124.846 111.341,124.846 115.845,127.614 118.556,127.614 115.845,128.362 118.563,128.362 115.845,129.198 118.577,129.198 164.988,134.328 163.422,134.343 159.481,145.284 164.577,145.284 166.589,145.284 160.193,145.304 161.182,145.303 162.039,145.293 163.863,145.303 166.846,146.249 138.895,146.369 138.216,146.384 139.696,146.384 142.812,146.569 141.336,146.789 145.437,146.809 138.515,147.007 139.211,147.007 143.33,147.113 141.862,147.333
Enable_Buffer_DCDC: J6.4
F\A\U\L\T\__Bat_H1_Buff: R3.1 U9.14 | length 17.6
  Top Layer w0.254: R3.1@139.372,129.198 139.372,126.474 144.779,121.066 144.779,117.758 144.473,117.452 144.152,117.452 143.926,117.226 ccw(c144.473,116.677) 143.924,117.224 143.604,116.903 143.604,116.475 143.056,115.927 U9.14@141.902,115.927
F\A\U\L\T\_Bat_H1_init: R34.2 U7.46 | length 24.3
  Top Layer w0.254: v1(117.447,105.38) 118.558,105.38 118.886,105.052 119.326,105.052 119.378,105 122.208,105 122.293,105.085 124.365,105.085 128.75,109.47 128.75,116.507 130.132,117.89 R34.2@131.136,117.89
  Bottom Layer w0.254: U7.46@116.508,105.544 116.606,105.446 117.313,105.446 117.379,105.38 v1(117.447,105.38)
F\A\U\L\T\_Bat_H2_Buff: R13.1 U14.14 | length 14.7
  Top Layer w0.254: U14.14@139.116,58.448 139.128,58.459 140.376,58.459 v1(140.387,58.471) ; v1@150.813,55.119 151.65,55.119 R13.1@151.968,54.801
  Layer 2 w0.254: v1(140.387,58.471) 140.376,58.459 143.914,58.459 147.553,54.82 148.987,54.82 149.286,55.119 v1@150.857,55.119
  other v1: 150.789,55.119
F\A\U\L\T\_Bat_H2_init: R59.2 U12.46 | length 16.4
  Top Layer w0.254: v1(114.482,56.339) 122.602,56.339 127.247,60.984 127.974,60.984 R59.2@127.979,60.99
  Bottom Layer w0.254: U12.46@113.462,56.339 v1(114.482,56.339)
F\A\U\L\T\_Bat_L1_init: R84.1 U10.46 | length 15
  Top Layer w0.254: v1(117.452,119.019) 117.52,119.019 117.672,118.866 121.558,118.866 122.383,119.691 122.383,126.895 123.375,127.887 R84.1@123.4,127.887
  Bottom Layer w0.254: U10.46@116.44,119.08 116.479,119.042 117.428,119.042 v1(117.452,119.019)
F\A\U\L\T\_Bat_L2_init: R76.1 U15.46 | length 23.3
  Top Layer w0.254: v1(114.637,69.529) 114.648,69.54 115.272,69.54 115.634,69.902 120.626,69.902 120.66,69.936 121.045,69.936 124.186,73.077 133.85,73.077 R76.1@134.867,72.06
  Bottom Layer w0.254: U15.46@113.462,69.656 114.51,69.656 v1(114.637,69.529)
F\A\U\L\T\_Boost1_init: R75.1 U1.46 | length 11.2
  Top Layer w0.254: R75.1@170.055,64.974 R75.1@170.09,65.009 v1@170.09,63.766
  Bottom Layer w0.254: v1(170.055,63.766) 171.877,63.766 176.351,59.292 U1.46@176.351,57.567
F\A\U\L\T\_Boost2_init: R83.1 U4.46 | length 9.7
  Top Layer w0.254: R83.1@221.207,70.673 221.207,69.59 v1(221.699,69.098)
  Bottom Layer w0.254: v1(221.699,69.098) 221.699,65.053 223.76,62.991 223.76,62.117 U4.46@223.842,62.035
F\A\U\L\T\_O\C\_Batt_H1_Buff: C14.2 J8.19 R4.2 | length 29.6
  Top Layer w0.254: R4.2@133.211,134.417 C14.2@133.211,135.936 133.236,135.936 133.584,136.284 133.584,137.216 136.469,140.101 136.469,140.544 v1(136.517,140.593)
  Layer 2 w0.254: v1(136.517,140.593) 136.524,140.599 136.524,157.43 137.501,158.407 139.228,158.407 140.122,157.513 140.122,157.166 J8.19@140.555,157.166
F\A\U\L\T\_O\C\_Batt_H2_Buff: C28.2 J8.14 R14.2 | length 122.3
  Top Layer w0.254: v1(154.139,131.231) 154.139,131.228 162.407,122.959 162.407,54.696 162.89,54.213 C28.2@162.89,52.728 R14.2@161.328,52.728
  Layer 2 w0.254: J8.14@144.298,155.916 143.442,155.059 141.108,155.059 140.401,154.353 140.401,137.402 147.524,130.279 153.187,130.279 v1(154.139,131.231)
F\A\U\L\T\_O\C\_Batt_L1_Buff: J8.21 U20.4 | length 31.2
  Top Layer w0.254: U20.4@127.458,135.645 127.458,137.044 133.083,142.669 v1(137.178,142.669)
  Layer 2 w0.254: v1(137.178,142.669) 137.178,157.513 137.668,158.003 138.362,158.003 138.852,157.513 138.852,157.166 J8.21@139.285,157.166
F\A\U\L\T\_O\C\_Batt_L2_Buff: J8.16 U18.4 | length 101
  Top Layer w0.254: U18.4@141.751,67.613 142.983,68.844 142.983,69.598 157.759,84.374 157.759,120.132 145.94,131.951 v1(145.94,137.336)
  Bottom Layer w0.254: J8.16@143.095,155.896 145.985,153.006 145.985,137.382 v1(145.94,137.336)
F\A\U\L\T\_O\C\_Boost1_Buff: J8.15 U17.4 | length 109.7
  Top Layer w0.254: v1(158.843,142.661) 158.843,133.039 167.116,124.766 167.116,112.192 169.516,109.792 169.516,76.997 U17.4@173.835,72.678
  Layer 2 w0.254: J8.15@143.095,157.166 143.147,157.218 143.147,157.937 146.363,161.153 154.064,161.153 158.843,156.374 v1(158.843,142.661)
F\A\U\L\T\_O\C\_Boost2_Buff: J8.17 U19.4 | length 149.5
  Top Layer w0.254: v1(174.498,109.71) 180.322,109.71 181.925,108.107 181.925,97.126 191.707,87.344 219.15,87.344 225.039,81.455 225.039,77.996 U19.4@225.212,77.823
  Layer 2 w0.254: J8.17@141.825,156.844 J8.17@141.825,157.166 141.825,158.27 145.668,162.113 153.844,162.113 165.934,150.022 165.934,116.366 172.547,109.753 v1@174.498,109.753
GND_HVN: C1.2 C16.1 C17.2 C19.1 C31.1 C32.2 C49.2 C57.2 C102.1 C103.1 C104.1 C105.1 C108.1 C112.1 C132.1 C144.2 C153.1 C154.2 C155.1 J6.23 J6.24 J8.23 J8.24 Q1.4 Q1.7 R41.2 R72.1 R106.2 R107.2 R111.2 R139.2 R140.1 R145.2 R146.1 R147.1 R148.2 R149.1 R150.1 R151.1 R153.1 R154.1 R160.2 R161.2 R162.2 R163.2 R164.2 R165.2 R166.2 TP34.1 TP35.1 TP36.1 TP38.1 U3.2 U3.5 U5.2 U5.5 U16.4 U21.5 U22.5 U23.4 | length 71.2
  Top Layer w0.254: v1(14.365,157.145) C155.1@16.108,157.145 ; v1(15.633,161.85) R41.2@16.858,161.85 16.858,161.019 16.286,160.447 C154.2@16.261,160.447 ; v1(21.803,162.545) 21.803,161.85 C153.1@21.728,161.775 22.525,161.775 23.613,160.687 23.613,160.171 U23.4@23.628,160.155 25.605,160.155 C104.1@25.708,160.258 ; R150.1@25.633,161.785 25.633,160.333 C104.1@25.708,160.258 ; R139.2@27.206,160.258 C104.1@25.708,160.258 ; v1(40.044,158.547) R145.2@40.044,157.194 C16.1@40.044,155.566 39.869,155.391 Q1.4@39.869,154.066 Q1.7@40.749,154.066 ; R147.1@48.214,156.777 R153.1@51.177,156.777 ; v1(51.177,155.491) 51.177,156.501 R153.1@51.433,156.757 ; R153.1@51.177,156.775 R154.1@54.126,156.775 ; C1.2@52.589,149.8 52.639,149.75 53.517,149.75 53.781,149.486 v1(53.85,149.486) ; v1(74.944,60.847) 76.09,60.847 C57.2@76.214,60.97 C57.2@76.15,61.034 ; U21.5@76.52,105.704 76.491,105.732 76.491,106.295 76.64,106.443 v1(77.105,106.443) ; C49.2@78.339,99.722 78.345,99.716 v1(79.519,99.716) ; U22.5@79.739,64.98 80.131,64.98 80.304,65.153 v1(80.304,65.779) ; R111.2@117.279,26.894 117.294,26.909 R140.1@117.294,29.02 C105.1@119.052,29.02 119.052,28.995 119.411,28.636 R151.1@119.411,27.325 119.411,26.065 v1(119.527,25.949) ; U16.4@121.051,29.335 U16.4@121.138,29.248 ; v1(121.138,28.509) U16.4@121.138,29.248 ; U16.4@121.824,29.162 121.224,29.162 U16.4@121.138,29.248 ; v1(123.311,24.469) 124.828,24.469 R107.2@124.93,24.571 124.93,26.114 R106.2@124.941,26.125 C103.1@124.941,27.6 124.891,27.65 R149.1@123.311,27.65 ; 123.315,141.15 123.341,141.124 C144.2@124.624,141.124 C144.2@124.645,141.103 ; v1(123.786,34.77) C102.1@124.941,34.77 ; J8.24@138.015,155.896 J8.23@138.015,157.166 ; v1(202.713,38.945) 203.954,38.945 C112.1@203.975,38.966 204.175,38.766 U5.2@205.881,38.766 ; v1(207.308,29.994) C19.1@208.77,29.994 ; C19.1@208.549,30.301 C19.1@208.813,30.037 C19.1@208.77,29.994 ; U5.5@208.631,38.766 208.831,38.766 209.033,38.564 R72.1@210.267,38.564 210.304,38.527 v1(210.304,37.373) ; U3.5@208.707,25.684 208.707,23.909 R146.1@208.606,23.809 208.606,22.765 208.738,22.634 v1(208.738,22.565) ; U3.2@208.707,28.434 208.707,29.931 C19.1@208.77,29.994 ; C32.2@211.867,41.512 C31.1@211.867,39.993 212.925,39.993 v1@212.932,40 ; C108.1@212.047,23.809 C17.2@212.047,22.357 213.168,22.357 213.298,22.227 v1(213.366,22.227)
  Layer 1 w0.254: J6.24@114.015,155.896 J6.23@114.015,157.166
  other v1: 212.925,40.019 174.007,98.258 174.563,98.258 164.697,98.372 176.494,98.372 177.17,98.372 164.678,99.434 166.687,99.434 174.007,99.434 174.603,99.434 176.178,99.434 167.878,101.022 174.02,101.022 165.011,101.538 166.687,101.565 167.878,101.558 174.007,101.565 174.853,102.065 165.029,102.535 166.687,102.544 167.874,102.544 164.992,104.55 167.467,105.033 164.992,106.013 167.005,106.013 168.007,106.013 167.042,107.033 68.357,127 76.024,127 84.488,127 92.584,127 100.139,127 106.13,127 64.227,130.5 71.894,130.5 80.358,130.5 88.454,130.5 96.009,130.5 102,130.5 60.5,134.5 68.167,134.5 76.631,134.5 84.727,134.5 92.282,134.5 98.273,134.5 121.81,138.788 97.289,139.43 58.688,139.5 66.355,139.5 74.819,139.5 82.915,139.5 90.47,139.5 123.145,139.982 125.877,139.982 123.159,140.818 125.877,140.818 123.166,141.565 60.034,146.195 67.701,146.195 76.165,146.195 84.261,146.195 91.816,146.195 97.807,146.195 127.033,146.763 121.917,146.99 127.033,148.425 131.785,148.425 157.353,150.465 158.034,150.469 159.773,150.465 160.916,150.465 162.206,150.465 163.416,150.465 164.706,150.465 166.455,150.465 131.785,150.474 60.034,152.065 67.701,152.065 76.165,152.065 84.261,152.065 91.816,152.065 97.807,152.065 131.785,152.668 134.14,152.668 141.092,152.668 138.362,152.732 139.711,152.732 143.523,152.732 145.243,152.732 146.963,152.732 126.908,153.006 127.826,153.076 141.092,153.268 144.533,153.268 130.319,153.32 147.886,153.355 139.073,153.392 127.485,153.644 124.945,153.704 131.785,153.704 134.115,153.733 60.034,153.969 67.701,153.969 76.165,153.969 84.261,153.969 91.816,153.969 97.807,153.969 128.449,154.027 125.604,154.353 127.885,154.408 109.279,156.437 111.534,156.437 109.279,158.118 111.534,158.118 111.534,159.6 109.279,159.616 109.261,160.673 111.552,160.673 109.279,161.606 111.552,161.606 62,162.668 69.667,162.668 78.131,162.668 86.227,162.668 93.782,162.668 99.773,162.668 111.534,162.668 111.552,163.73
IN_PWM_Bat_H1: R24.1 R38.2 | length 10.4
  Top Layer w0.254: R24.1@121.593,107.167 125.593,107.167 126.033,107.608 v1(126.05,107.608) ; v1(129.484,108.311) 129.943,108.77 130.788,108.77 R38.2@131.136,109.118
  Layer 2 w0.254: v1(126.05,107.608) 128.793,107.608 129.484,108.298 v1(129.484,108.311)
IN_PWM_Bat_H2: R49.1 R63.2 | length 13.1
  Top Layer w0.254: R49.1@120.669,58.915 R49.1@120.67,58.916 ; R49.1@120.929,58.835 123.33,58.835 123.667,58.499 v1(123.736,58.499) ; v1(124.291,52.405) 124.36,52.405 124.62,52.144 R63.2@127.979,52.144
  Layer 2 w0.254: v1(123.736,58.499) 124.291,57.943 v1(124.291,52.405)
NetC2_2: C2.2 K1.6 L18.4 L18.5 L18.6 R88.2
NetC7_2: C7.2 R1.2 U1.45 | length 4.7
  Top Layer w0.254: R1.2@174.576,61.695 C7.2@174.576,60.312 174.601,60.312 175.652,59.261 175.652,58.935 v1(175.701,58.887)
  Bottom Layer w0.254: U1.45@175.701,57.567 v1(175.701,58.887) v1@175.701,58.984
NetC8_2: C8.2 U1.51 | length 2.9
  Top Layer w0.254: C8.2@179.567,60.415 179.601,60.381 v1(179.601,58.935)
  Bottom Layer w0.254: U1.51@179.601,57.567 v1(179.601,58.935)
NetC11_2: C11.2 R3.2 R39.2 U8.1 | length 5.1
  Top Layer w0.254: U8.1@134.364,130.835 136.106,130.835 C11.2@136.143,130.798 137.771,130.798 R3.2@139.434,130.798
NetC12_2: C12.2 R6.2 U1.50 | length 6
  Top Layer w0.254: R6.2@176.351,61.94 176.3,61.889 176.3,60.644 176.724,60.22 176.724,60.195 177.565,59.354 178.477,59.354 v1(178.944,58.886)
  Bottom Layer w0.254: v1(178.944,58.886) 178.948,58.883 178.948,57.57 U1.50@178.951,57.567
NetC13_1: C13.1 D17.1 U1.40 U1.41 | length 6.5
  Top Layer w0.254: C13.1@170.237,57.768 170.237,56.752 170.348,56.641 170.348,56.282 170.471,56.159 D17.1@170.746,56.159 170.771,56.134 173.516,56.134 v1(173.541,56.109)
  Bottom Layer w0.254: U1.40@172.591,55.417 U1.41@172.591,56.067 ; U1.41@172.591,56.057 172.634,56.014 172.677,56.057 173.42,56.057 173.472,56.109 v1(173.541,56.109)
NetC15_2: C15.2 R5.2 R64.2 U8.2 | length 5.3
  Top Layer w0.254: U8.2@134.364,131.785 135.493,131.785 136.143,132.435 136.143,132.46 R64.2@137.739,132.46 139.368,132.46 R5.2@139.37,132.461
NetC16_2: C16.2 Q1.3 R144.2 R145.1 | length 5.4
  Top Layer w0.254: R145.1@41.644,157.194 C16.2@41.644,155.566 ; Q1.3@41.819,154.066 41.819,155.391 C16.2@41.644,155.566 ; R144.2@43.266,154.291 43.266,154.316 42.918,154.664 42.571,154.664 41.669,155.566 C16.2@41.644,155.566
NetC17_1: C17.1 C108.2 FB1.2 U3.6 | length 5
  Top Layer w0.254: C17.1@210.201,22.408 210.201,23.809 210.201,24.939 209.657,25.484 U3.6@209.657,25.684 210.732,25.684 FB1.2@211.032,25.384
NetC18_1: C18.1 R9.2 U3.3 | length 4
  Top Layer w0.254: R9.2@204.104,27.69 205.718,27.69 C18.1@205.75,27.657 205.75,27.682 206.502,28.434 U3.3@207.757,28.434
NetC18_2: C18.2 R10.2 U3.4 | length 3.8
  Top Layer w0.254: R10.2@204.104,25.982 205.8,25.982 206.099,25.684 U3.4@207.757,25.684
NetC21_2: C21.2 U4.51 | length 3
  Top Layer w0.254: v1(227.123,63.567) C21.2@227.123,64.985
  Bottom Layer w0.254: U4.51@227.092,62.035 227.107,62.051 227.107,63.551 v1(227.123,63.567)
NetC22_2: C22.2 R11.2 U4.45 | length 5.5
  Top Layer w0.254: v1(221.248,63.049) 221.248,64.394 C22.2@221.252,64.398 221.252,65.86 R11.2@221.265,65.873
  Bottom Layer w0.254: v1(221.248,63.049) 222.691,63.049 223.094,62.646 223.094,62.133 U4.45@223.192,62.035
NetC25_2: C25.2 R13.2 R156.2 U13.1 | length 5.1
  Top Layer w0.254: R13.2@151.968,53.201 R156.2@153.585,53.201 C25.2@155.201,53.201 155.374,53.028 U13.1@156.98,53.028
NetC26_2: C26.2 R16.2 U4.50 | length 5.6
  Top Layer w0.254: C26.2@224.057,65.126 R16.2@224.057,66.671 ; C26.2@224.428,64.751 225.612,63.567 v1(226.398,63.567)
  Bottom Layer w0.254: v1(226.398,63.567) 226.42,63.545 226.42,62.057 U4.50@226.442,62.035
NetC27_1: C27.1 D18.1 U4.40 U4.41 | length 6.2
  Top Layer w0.254: D18.1@218.974,57.645 219.025,57.696 219.025,58.204 219.588,58.768 C27.1@219.588,59.925 219.588,60.09 220.096,60.598 220.98,60.598 221.032,60.65 v1@221.1,60.65
  Bottom Layer w0.254: U4.40@220.082,59.885 U4.41@220.082,60.535 220.148,60.602 221.052,60.602 v1@221.1,60.65
  other v1: 221.263,60.65
NetC29_2: C29.2 R15.2 R157.2 U13.2 | length 5.3
  Top Layer w0.254: R15.2@151.97,51.378 R157.2@153.586,51.378 C29.2@155.203,51.378 155.203,51.403 155.878,52.078 U13.2@156.98,52.078
NetC31_2: C31.2 C32.1 FB2.2 U5.6 | length 4.9
  Top Layer w0.254: U5.6@208.631,39.716 209.99,39.716 C31.2@210.267,39.993 C32.1@210.267,41.512 210.18,41.599 FB2.2@210.18,43.108
NetC33_1: C33.1 R20.2 U5.3 | length 3.5
  Top Layer w0.254: R20.2@205.456,34.593 205.456,37.591 205.681,37.816 U5.3@205.881,37.816
NetC33_2: C33.2 R71.2 U5.4 | length 4
  Top Layer w0.254: C33.2@207.056,36.064 C33.2@207.081,36.064 ; R71.2@208.556,36.083 208.537,36.064 C33.2@207.081,36.064 ; U5.4@208.631,37.816 208.431,37.816 207.429,36.814 207.429,36.412 C33.2@207.081,36.064
NetC35_2: C35.2 R24.2 U7.45 | length 5
  Top Layer w0.254: v1(117.494,106.084) 118.425,106.084 118.758,105.752 C35.2@119.993,105.752 ; C35.2@119.993,105.808 R24.2@119.993,107.167
  Bottom Layer w0.254: U7.45@116.508,106.194 116.535,106.167 117.468,106.167 v1@117.494,106.141
NetC39_2: C39.2 C43.1 FB4.2 U6.6 U6.7 | length 5.9
  Top Layer w0.254: U6.6@146.395,103.317 U6.7@146.395,103.967 148.274,103.967 C43.1@148.424,103.817 148.524,103.717 C39.2@150.063,103.717 150.263,103.917 FB4.2@151.479,103.917
NetC42_1: C42.1 R23.2 R29.1 U6.33 U6.34 | length 6.3
  Top Layer w0.254: R29.1@132.276,102.011 C42.1@133.876,102.011 ; R23.2@133.876,103.517 C42.1@133.876,102.011 ; U6.34@136.445,101.367 U6.33@136.445,102.017 133.881,102.017 C42.1@133.876,102.011
NetC44_1: C44.1 R58.2 U21.2 | length 3.3
  Top Layer w0.254: U21.2@87.42,103.164 89.172,103.164 C44.1@89.337,102.999 89.392,102.944 R58.2@90.649,102.944
NetC44_2: C44.2 R56.2 U21.3 | length 3.3
  Top Layer w0.254: U21.3@87.42,104.434 89.171,104.434 C44.2@89.337,104.599 90.615,104.599 R56.2@90.649,104.634
NetC45_2: C45.2 R32.2 U7.50 | length 4.8
  Top Layer w0.254: v1(118.461,102.899) 118.53,102.899 118.932,103.301 119.976,103.301 C45.2@120.021,103.256 ; C45.2@120.031,103.211 R32.2@121.067,103.211
  Bottom Layer w0.254: U7.50@116.508,102.944 116.516,102.936 118.425,102.936 v1(118.461,102.899)
NetC46_1: C46.1 D19.1 U7.40 U7.41 | length 5.3
  Top Layer w0.254: v2(115.39,108.334) 115.39,108.896 C46.1@115.71,109.217 116.218,108.709 116.851,108.709 117.134,108.426 D19.1@117.409,108.426
  Bottom Layer w0.254: U7.41@115.008,109.304 U7.40@114.358,109.304 114.358,108.954 114.456,108.856 114.783,108.856 114.964,108.675 114.98,108.675 115.321,108.334 v2(115.39,108.334)
NetC47_2: C47.2 R25.2 R27.2 U6.4 | length 10.3
  Top Layer w0.254: U6.4@146.395,102.017 147.701,102.017 148.392,102.707 152.488,102.707 152.656,102.54 152.681,102.54 C47.2@153.029,102.192 ; C47.2@153.029,102.167 C47.2@153.029,102.192 ; R27.2@154.527,103.817 153.029,103.817 C47.2@153.029,102.192
NetC48_1: C48.1 FB5.2 TP7.1 U21.1 | length 6
  Top Layer w0.254: U21.1@86.947,101.721 87.12,101.894 88.875,101.894 89.362,101.407 C48.1@89.387,101.407 89.387,100.12 FB5.2@89.115,99.847 TP7.1@87.531,99.847
NetC49_1: C49.1 FB12.2 U21.8 | length 4.1
  Top Layer w0.254: U21.8@76.491,101.922 U21.8@76.52,101.894 76.52,99.941 C49.1@76.739,99.722 76.839,99.622 FB12.2@76.839,97.971
NetC50_1: C50.1 FB9.2 U9.16 | length 3.3
  Top Layer w0.254: FB9.2@141.419,120.244 141.419,119.194 141.909,118.704 C50.1@141.934,118.704 141.902,118.672 U9.16@141.902,117.197
NetC53_1: C53.1 R96.2 U22.2 | length 3.6
  Top Layer w0.254: U22.2@90.639,62.44 91.239,62.44 91.45,62.23 C53.1@92.68,62.23 R96.2@94.12,62.23
NetC53_2: C53.2 R67.2 U22.3 | length 6.1
  Top Layer w0.254: U22.3@90.639,63.71 92.561,63.71 C53.2@92.68,63.83 94.559,63.83 95.535,62.854 95.535,62.495 95.697,62.333 R67.2@95.836,62.333
NetC54_2: C54.2 R155.1 U9.5 | length 6.3
  Top Layer w0.254: R155.1@132.736,110.59 C54.2@132.736,112.09 132.761,112.09 135.327,114.657 U9.5@136.452,114.657
NetC55_2: C55.2 R34.1 U9.3 | length 5.3
  Top Layer w0.254: R34.1@132.736,117.89 C55.2@132.736,116.516 132.761,116.516 133.35,115.927 U9.3@136.452,115.927
NetC56_1: C56.1 FB14.2 TP8.1 U22.1 | length 4.9
  Top Layer w0.254: TP8.1@89.131,58.41 89.216,58.41 89.653,57.973 90.626,57.973 90.626,59.597 C56.1@90.639,59.611 U22.1@90.639,61.17
NetC57_1: C57.1 FB13.2 U22.8 | length 3.8
  Top Layer w0.254: FB13.2@77.993,59.23 77.993,60.791 C57.1@77.814,60.97 78.014,61.17 U22.8@79.739,61.17
NetC58_2: C58.2 R37.2 U9.11 | length 4.9
  Top Layer w0.254: U9.11@141.902,114.022 143.791,114.022 144.255,114.486 144.658,114.486 144.959,114.787 R37.2@144.959,113.261
NetC61_2: C61.2 U10.51 | length 2.2
  Top Layer w0.254: C61.2@117.268,114.535 117.495,114.761 v1(117.495,115.438)
  Bottom Layer w0.254: U10.51@116.424,115.846 116.522,115.748 117.116,115.748 117.427,115.438 v1(117.495,115.438)
NetC62_2: C62.2 R40.2 U10.45 | length 4.7
  Top Layer w0.254: v1(117.526,119.672) 117.546,119.693 118.161,119.693 118.288,119.82 C62.2@119.505,119.82 R40.2@121.011,119.82
  Bottom Layer w0.254: U10.45@116.436,119.734 116.477,119.694 117.504,119.694 v1(117.526,119.672)
NetC63_1: C63.1 R94.1 | length 3.5
  Top Layer w0.254: C63.1@102.113,49.054 103.609,49.054 104.282,49.727 R94.1@104.282,50.74
NetC64_2: C64.2 R45.2 U10.50 | length 4.8
  Top Layer w0.254: v1(117.457,116.5) 117.526,116.5 117.653,116.627 117.679,116.627 117.805,116.752 C64.2@119.576,116.752 R45.2@121.085,116.752
  Bottom Layer w0.254: U10.50@116.424,116.496 116.426,116.498 v1(117.457,116.5) v1(117.457,116.5)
